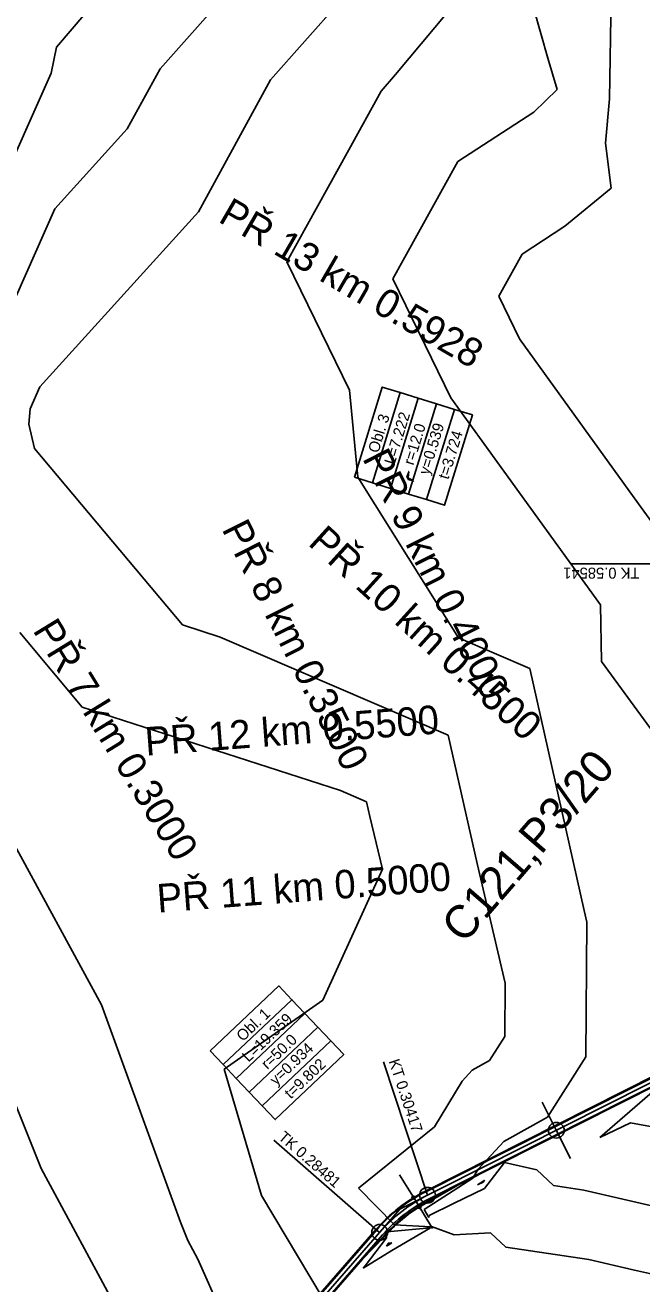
# Model space of a CAD drawing. Extents: x -549394 to -546608, y -1037055 to -1033629.
# Drawn here: x -548134.2 to -547938.3, y -1034859.6 to -1034459.8 of the extents above; entities that cross this region are included whole.
import ezdxf

# ---------------------------------------------------------------- set-up
doc = ezdxf.new("R2010")
doc.units = 0
for name, color, linetype in [('hlavni_vrst', 7, 'Continuous'), ('norm_vrst', 7, 'Continuous'), ('POLYGONY_SITUACE_PO', 7, 'Continuous'), ('u_sirka_0_5m', 7, 'Continuous'), ('u_sirka_1_0m', 7, 'Continuous'), ('x_navrh_C121', 7, 'Continuous'), ('x_osa_C121', 7, 'Continuous'), ('x_popis_oblouky_C121', 7, 'Continuous'), ('x_popis_pricne_rezy_C121', 7, 'Continuous'), ('x_popis_velky_C121', 7, 'Continuous')]:
    doc.layers.add(name, color=color, linetype=linetype)

msp = doc.modelspace()

# ---------------------------------------------------------------- linework, layer by layer
at = {"layer": 'hlavni_vrst'}
for p, q in [((-547968.22, -1034470.29), (-547972.63, -1034454.59)), ((-547965.24, -1034480.24), (-547968.22, -1034470.29)), ((-547972.63, -1034487.41), (-547965.24, -1034480.24)), ((-547996.78, -1034503.15), (-547972.63, -1034487.41)), ((-548017.39, -1034540.43), (-547996.78, -1034503.15)), ((-547998.99, -1034578.18), (-548017.39, -1034540.43)), ((-547982.19, -1034601.45), (-547998.99, -1034578.18)), ((-547951.4, -1034643.89), (-547982.19, -1034601.45)), ((-547951.14, -1034661.91), (-547951.4, -1034643.89)), ((-547933.58, -1034685.98), (-547951.14, -1034661.91)), ((-548129.19, -1034823), (-548140.96, -1034793.3)), ((-547951.64, -1034813.16), (-547931.04, -1034795.2)), ((-547941.92, -1034808.45), (-547951.64, -1034813.16)), ((-547924.61, -1034811.63), (-547941.92, -1034808.45)), ((-548102.99, -1034871.31), (-548129.19, -1034823)), ((-547990.49, -1034828.14), (-547988.82, -1034827.07)), ((-547988.74, -1034827.29), (-547990.49, -1034828.14)), ((-547988.82, -1034827.07), (-547988.28, -1034826.69)), ((-547988.28, -1034826.69), (-547988.74, -1034827.29))]:
    msp.add_line(p, q, dxfattribs=at)
at = {"layer": 'norm_vrst'}
for p, q in [((-548124.25, -1034466.77), (-548083.54, -1034418.98)), ((-548091.3, -1034473.64), (-548052.38, -1034429.67)), ((-548016.54, -1034475.52), (-547994.11, -1034448.52)), ((-547948.63, -1034483.2), (-547948, -1034448.39)), ((-548056.24, -1034477.2), (-548034.46, -1034452.59)), ((-548125.98, -1034475.07), (-548124.25, -1034466.77)), ((-548159.45, -1034550.3), (-548125.98, -1034475.07)), ((-548101.78, -1034492.75), (-548091.3, -1034473.64)), ((-548021.17, -1034480.75), (-548016.54, -1034475.52)), ((-548079.18, -1034519.05), (-548056.24, -1034477.2)), ((-548031.4, -1034499.41), (-548021.17, -1034480.75)), ((-547949.87, -1034497.33), (-547948.63, -1034483.2)), ((-548124.79, -1034518.16), (-548101.78, -1034492.75)), ((-548051.05, -1034534.94), (-548031.4, -1034499.41)), ((-547948.03, -1034511.62), (-547949.87, -1034497.33)), ((-547962.73, -1034523.65), (-547948.03, -1034511.62)), ((-548146.06, -1034565.97), (-548124.79, -1034518.16)), ((-548129.58, -1034574.7), (-548079.18, -1034519.05)), ((-547976.34, -1034532.53), (-547962.73, -1034523.65)), ((-548031.16, -1034575.74), (-548051.05, -1034534.94)), ((-547983.74, -1034545.91), (-547976.34, -1034532.53)), ((-547977.13, -1034559.46), (-547983.74, -1034545.91)), ((-547939.34, -1034611.82), (-547977.13, -1034559.46)), ((-548132.68, -1034581.65), (-548129.58, -1034574.7)), ((-548028.57, -1034603.4), (-548031.16, -1034575.74)), ((-548133.11, -1034586.55), (-548132.68, -1034581.65)), ((-548131.21, -1034594.26), (-548133.11, -1034586.55)), ((-548084.19, -1034650.32), (-548131.21, -1034594.26)), ((-547996.51, -1034654.45), (-548028.57, -1034603.4)), ((-547930.54, -1034623.95), (-547939.34, -1034611.82)), ((-548072.27, -1034654.17), (-548084.19, -1034650.32)), ((-548116.13, -1034676.43), (-548135.97, -1034652.77)), ((-547999.8, -1034685.36), (-548072.27, -1034654.17)), ((-547973.84, -1034664.21), (-547996.51, -1034654.45)), ((-547956.64, -1034741.01), (-547973.84, -1034664.21)), ((-548034.09, -1034702.92), (-548116.13, -1034676.43)), ((-547990.67, -1034726.1), (-547999.8, -1034685.36)), ((-548025.76, -1034706.51), (-548034.09, -1034702.92)), ((-548024.71, -1034711.2), (-548025.76, -1034706.51)), ((-548020.75, -1034727.95), (-548024.71, -1034711.2)), ((-548109.97, -1034770.99), (-548138.9, -1034717.87)), ((-548039.64, -1034769.5), (-548020.75, -1034727.95)), ((-547981.7, -1034764.08), (-547990.67, -1034726.1)), ((-547955.75, -1034744.77), (-547956.64, -1034741.01)), ((-547956.05, -1034787.56), (-547955.75, -1034744.77)), ((-547981.82, -1034781.1), (-547981.7, -1034764.08)), ((-548084.86, -1034840.06), (-548109.97, -1034770.99)), ((-548070.96, -1034791.48), (-548039.64, -1034769.5)), ((-547986.68, -1034788.68), (-547981.82, -1034781.1)), ((-547968.28, -1034806.63), (-547956.05, -1034787.56)), ((-548059.11, -1034831.52), (-548070.96, -1034791.48)), ((-547995.42, -1034795.27), (-547992.19, -1034791.77)), ((-547992.19, -1034791.77), (-547986.68, -1034788.68)), ((-548004.18, -1034809.72), (-547995.42, -1034795.27)), ((-547982.15, -1034814.41), (-547968.28, -1034806.63)), ((-548028.31, -1034829.28), (-548004.18, -1034809.72)), ((-547990.28, -1034823.21), (-547982.15, -1034814.41)), ((-547991.97, -1034826.01), (-547990.28, -1034823.21)), ((-547981.95, -1034821.06), (-547988.27, -1034829.32)), ((-547971.69, -1034823.37), (-547981.95, -1034821.06)), ((-547966.4, -1034828.41), (-547971.69, -1034823.37)), ((-548007.41, -1034835.99), (-547991.97, -1034826.01)), ((-548039.89, -1034863.86), (-548059.11, -1034831.52)), ((-548016.86, -1034840.89), (-548028.31, -1034829.28)), ((-547988.27, -1034829.32), (-547998.17, -1034834.14)), ((-547956.72, -1034829.83), (-547966.4, -1034828.41)), ((-547927.5, -1034836.66), (-547956.72, -1034829.83)), ((-547998.17, -1034834.14), (-548005.82, -1034837.88)), ((-548006, -1034838.59), (-548007.41, -1034835.99)), ((-548005.82, -1034837.88), (-548006, -1034838.59)), ((-548082.56, -1034845.87), (-548084.86, -1034840.06)), ((-548019.45, -1034844.98), (-548019.3, -1034843.12)), ((-548019.3, -1034843.12), (-548005.47, -1034841.82)), ((-548005.47, -1034841.82), (-548017.71, -1034849.03)), ((-548005.35, -1034841.47), (-548016.86, -1034840.89)), ((-548005.25, -1034841.66), (-548005.35, -1034841.47)), ((-548005.18, -1034841.41), (-548005.25, -1034841.66)), ((-547997.95, -1034844.08), (-548005.18, -1034841.41)), ((-547986.35, -1034843.44), (-547997.95, -1034844.08)), ((-547981.54, -1034848.01), (-547986.35, -1034843.44)), ((-548079.34, -1034851.8), (-548082.56, -1034845.87)), ((-548026.18, -1034853.86), (-548019.45, -1034844.98)), ((-548018.72, -1034847.22), (-548019.47, -1034847.69)), ((-548019.47, -1034847.69), (-548019.42, -1034847.62)), ((-548019.42, -1034847.62), (-548018.86, -1034846.89)), ((-548018.86, -1034846.89), (-548018.85, -1034846.73)), ((-548018.85, -1034846.73), (-548017.71, -1034846.63)), ((-548017.71, -1034846.63), (-548018.72, -1034847.22)), ((-548066.23, -1034881.33), (-548079.34, -1034851.8)), ((-548017.71, -1034849.03), (-548026.84, -1034854.66)), ((-547955.18, -1034851.89), (-547981.54, -1034848.01)), ((-547940.64, -1034855.29), (-547955.18, -1034851.89)), ((-548026.84, -1034854.66), (-548026.18, -1034853.86)), ((-547922.42, -1034859.39), (-547940.64, -1034855.29))]:
    msp.add_line(p, q, dxfattribs=at)
at = {"layer": 'POLYGONY_SITUACE_PO'}
for centre in [(-548006.41, -1034831.47), (-548021.6, -1034843.27)]:
    msp.add_circle(centre, 2.5, dxfattribs=at)
at = {"layer": 'u_sirka_0_5m'}
for centre in [(-548010.83, -1034832.22), (-548008.99, -1034835.23)]:
    msp.add_circle(centre, 0.5, dxfattribs=at)
at = {"layer": 'u_sirka_1_0m'}
msp.add_circle((-547965.48, -1034810.84), 2.5, dxfattribs=at)
at = {"layer": 'x_navrh_C121'}
for p, q in [((-548006.97, -1034830.35), (-547882.64, -1034767.69)), ((-548005.85, -1034832.58), (-547881.52, -1034769.92)), ((-548005.61, -1034833.06), (-547996.92, -1034828.08)), ((-548005.49, -1034833.28), (-547996.8, -1034828.3)), ((-548208.33, -1035055.65), (-548022.55, -1034842.45)), ((-548206.76, -1035057.65), (-548020.66, -1034844.09)), ((-548020.26, -1034844.44), (-548027.23, -1034851.63)), ((-548020.08, -1034844.61), (-548027.05, -1034851.8))]:
    msp.add_line(p, q, dxfattribs=at)
for points in [[(-548007.09, -1034830.13), (-547891.7, -1034771.97)], [(-547996.8, -1034828.3), (-547881.4, -1034770.15)], [(-548198.55, -1035044.05), (-548022.74, -1034842.28)], [(-548203.31, -1035054.08), (-548027.05, -1034851.8)]]:
    msp.add_lwpolyline(points, dxfattribs=at)
for radius, start, end in [(51.5, 116.7478, 138.9312), (51.25, 116.7478, 138.9312), (48.75, 116.7478, 138.9312), (48.22, 116.7478, 138.9312), (47.97, 116.7399, 138.9391)]:
    msp.add_arc((-547983.91, -1034876.12), radius, start, end, dxfattribs=at)
at = {"layer": 'x_osa_C121'}
for points in [[(-548015.16, -1034835.88), (-547871.32, -1034763.38)], [(-548208.71, -1035057.99), (-548015.16, -1034835.88)]]:
    msp.add_lwpolyline(points, dxfattribs=at)
msp.add_arc((-547983.91, -1034876.12), 50, 116.7478, 138.9312, dxfattribs=at)
at = {"layer": 'x_popis_oblouky_C121'}
for points in [[(-548029.63, -1034603.42), (-548020.78, -1034574.76), (-548015.05, -1034576.53), (-548023.9, -1034605.19)], [(-548023.9, -1034605.19), (-548015.05, -1034576.53), (-548009.32, -1034578.3), (-548018.17, -1034606.96)], [(-548018.17, -1034606.96), (-548009.32, -1034578.3), (-548003.58, -1034580.07), (-548012.44, -1034608.73)], [(-548012.44, -1034608.73), (-548003.58, -1034580.07), (-547997.85, -1034581.84), (-548006.7, -1034610.51)], [(-548006.7, -1034610.51), (-547997.85, -1034581.84), (-547992.12, -1034583.61), (-548000.97, -1034612.28)], [(-548075.41, -1034785.63), (-548053.63, -1034765.01), (-548049.5, -1034769.36), (-548071.29, -1034789.99)], [(-548071.29, -1034789.99), (-548049.5, -1034769.36), (-548045.38, -1034773.72), (-548067.16, -1034794.35)], [(-548067.16, -1034794.35), (-548045.38, -1034773.72), (-548041.25, -1034778.08), (-548063.04, -1034798.7)], [(-548063.04, -1034798.7), (-548041.25, -1034778.08), (-548037.13, -1034782.43), (-548058.91, -1034803.06)], [(-548058.91, -1034803.06), (-548037.13, -1034782.43), (-548033, -1034786.79), (-548054.78, -1034807.42)]]:
    msp.add_lwpolyline(points, close=True, dxfattribs=at)
for points in [[(-547961.01, -1034630.88), (-547895.1, -1034630.93)], [(-548020.39, -1034789.14), (-548006.41, -1034831.47)], [(-548055.21, -1034813.99), (-548021.6, -1034843.27)]]:
    msp.add_lwpolyline(points, dxfattribs=at)
at = {"layer": 'x_popis_pricne_rezy_C121'}
for points in [[(-547969.98, -1034801.91), (-547965.48, -1034810.84), (-547960.98, -1034819.77)], [(-548015.28, -1034824.97), (-548010.05, -1034833.5), (-548004.82, -1034842.02)]]:
    msp.add_lwpolyline(points, dxfattribs=at)

# ---------------------------------------------------------------- texts
at = {"layer": 'x_popis_oblouky_C121'}
for s, rotation, p in [('Obl. 3', 72.86, (-548022.03, -1034595.92)), ('L=7.222', 72.86, (-548016.9, -1034599.64)), ('r=12.0', 72.86, (-548010.85, -1034599.8)), ('y=0.539', 72.86, (-548005.98, -1034602.89)), ('t=3.724', 72.86, (-547999.78, -1034604.32)), ('TK 0.58541', 179.9605, (-547939.08, -1034632.13)), ('Obl. 1', 43.4629, (-548065.1, -1034782.83)), ('L=19.359', 43.4629, (-548063.3, -1034789.39)), ('r=50.0', 43.4629, (-548057.27, -1034791.7)), ('y=0.934', 43.4629, (-548054.54, -1034796.78)), ('t=9.802', 43.4629, (-548049.84, -1034801.07)), ('KT 0.30417', 288.2759, (-548018.77, -1034788.87)), ('TK 0.28481', 318.9312, (-548054.07, -1034813.44))]:
    msp.add_text(s, height=3.5, rotation=rotation, dxfattribs=at).set_placement(p)
at = {"layer": 'x_popis_pricne_rezy_C121'}
for s, rotation, p in [('PŘ 13 km 0.5928', 329.8721, (-548073.23, -1034522.07)), ('PŘ 9 km 0.4000', 296.7478, (-548027.24, -1034597.35)), ('PŘ 8 km 0.3500', 296.7478, (-548071.89, -1034619.85)), ('PŘ 10 km 0.4500', 317.7665, (-548044.68, -1034624.71)), ('PŘ 7 km 0.3000', 301.5228, (-548131.99, -1034652.03)), ('PŘ 12 km 0.5500', 4.3542, (-548095.84, -1034691.87)), ('PŘ 11 km 0.5000', 4.3542, (-548092.04, -1034741.72))]:
    msp.add_text(s, height=9.0627, rotation=rotation, dxfattribs=at).set_placement(p)
at = {"layer": 'x_popis_velky_C121'}
msp.add_text('C121,P3/20', height=10.5, rotation=49.1557, dxfattribs=at).set_placement((-547994.84, -1034751.94))

doc.saveas('drawing.dxf')
